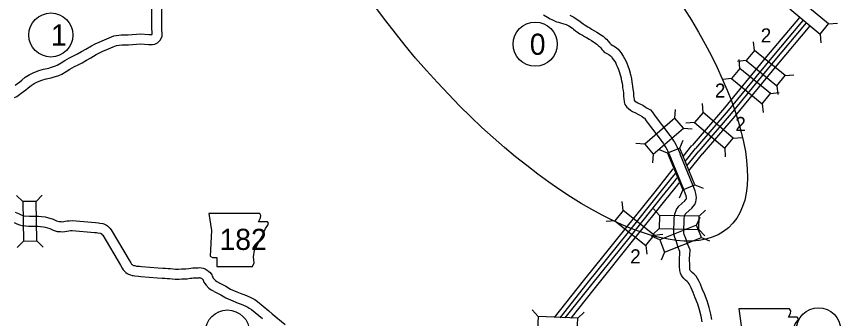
# Model space of a CAD drawing. Extents: x 1369979 to 1371646, y 379997 to 381064.
# Drawn here: x 1370115.6 to 1370308.4, y 380809.4 to 380880.1 of the extents above; entities that cross this region are included whole.
import ezdxf

# ---------------------------------------------------------------- set-up
doc = ezdxf.new("R2010")
doc.units = 0
doc.layers.add('R_Border Notes', color=7, linetype='Continuous')
doc.layers.add('R_Draft', color=7, linetype='Continuous')

msp = doc.modelspace()

# ---------------------------------------------------------------- linework, layer by layer
at = {"layer": 'R_Border Notes'}
for p, q in [((1370305.57, 380878.36), (1370307.63, 380878.55)), ((1370303.59, 380875.99), (1370303.78, 380873.93)), ((1370288.25, 380872.15), (1370288.04, 380874.2)), ((1370286.28, 380869.76), (1370284.23, 380869.55)), ((1370284.81, 380867.96), (1370284.61, 380870.01)), ((1370295.42, 380866.26), (1370297.47, 380866.46)), ((1370282.85, 380865.57), (1370280.8, 380865.37)), ((1370291.99, 380862.08), (1370294.04, 380862.28)), ((1370293.46, 380863.87), (1370293.66, 380861.82)), ((1370269.58, 380856.27), (1370269.74, 380858.33)), ((1370276.24, 380857.65), (1370276.08, 380859.71)), ((1370290.03, 380859.68), (1370290.23, 380857.63)), ((1370274.22, 380855.31), (1370272.16, 380855.15)), ((1370271.6, 380853.93), (1370273.66, 380853.77)), ((1370270.78, 380849.25), (1370271.58, 380851.15)), ((1370283.27, 380851.6), (1370285.33, 380851.76)), ((1370262.55, 380850.22), (1370260.49, 380850.38)), ((1370267.92, 380848.08), (1370266.02, 380848.87)), ((1370281.26, 380849.26), (1370281.41, 380847.2)), ((1370264.56, 380847.88), (1370264.41, 380845.82)), ((1370271.44, 380839.49), (1370270.65, 380837.59)), ((1370274.31, 380840.66), (1370276.21, 380839.87)), ((1370117.07, 380836.76), (1370115.59, 380838.19)), ((1370120.16, 380836.81), (1370121.6, 380838.29)), ((1370257.53, 380834.7), (1370257.3, 380836.75)), ((1370266, 380833.53), (1370264.58, 380835.02)), ((1370274.69, 380831.22), (1370275.51, 380833.12)), ((1370275.28, 380833.32), (1370276.77, 380834.75)), ((1370255.59, 380832.28), (1370253.54, 380832.05)), ((1370265.93, 380830.44), (1370264.44, 380829.01)), ((1370275.21, 380830.23), (1370276.64, 380828.74)), ((1370117.21, 380827.48), (1370115.78, 380826)), ((1370120.31, 380827.53), (1370121.79, 380826.09)), ((1370266.06, 380827.81), (1370264.16, 380828.64)), ((1370264.78, 380828.9), (1370266.83, 380829.13)), ((1370275.82, 380828.35), (1370277.72, 380827.53)), ((1370262.85, 380826.49), (1370263.08, 380824.44)), ((1370267.19, 380824.94), (1370266.37, 380823.05)), ((1370237.6, 380809.85), (1370236.21, 380811.37)), ((1370246.88, 380809.44), (1370248.4, 380810.84))]:
    msp.add_line(p, q, dxfattribs=at)
for points in [[(1370115.14, 380861.16), (1370115.63, 380861.4), (1370116.26, 380861.81), (1370116.68, 380862.16), (1370117.22, 380862.54), (1370117.79, 380862.96), (1370118.3, 380863.39), (1370118.99, 380863.93), (1370119.72, 380864.39), (1370120.47, 380864.81), (1370121.54, 380865.21), (1370122.49, 380865.51), (1370123.67, 380865.76), (1370124.16, 380865.9), (1370125.51, 380866.32), (1370126.2, 380866.61), (1370127.2, 380867.24), (1370128.1, 380867.74), (1370129.16, 380868.37), (1370129.82, 380868.72), (1370130.93, 380869.25), (1370131.99, 380869.84), (1370132.99, 380870.44), (1370134.26, 380871.23), (1370134.98, 380871.61), (1370135.81, 380871.96), (1370137.13, 380872.5), (1370138.19, 380872.97), (1370139.01, 380873.28), (1370140.22, 380873.49), (1370141.8, 380873.44), (1370144.63, 380873.67), (1370146.46, 380873.52), (1370146.91, 380873.53), (1370147.38, 380873.55), (1370147.91, 380873.61), (1370148.61, 380873.9), (1370149.21, 380874.58), (1370149.69, 380875.43), (1370149.62, 380877.72), (1370149.7, 380890.06)], [(1370115.26, 380864.03), (1370115.85, 380864.44), (1370116.33, 380864.8), (1370116.82, 380865.21), (1370117.65, 380865.86), (1370118.52, 380866.41), (1370119.48, 380866.94), (1370120.78, 380867.43), (1370121.9, 380867.78), (1370123.12, 380868.04), (1370123.51, 380868.15), (1370124.7, 380868.52), (1370125.11, 380868.7), (1370126, 380869.25), (1370126.93, 380869.77), (1370128.02, 380870.42), (1370128.77, 380870.82), (1370129.85, 380871.33), (1370130.81, 380871.87), (1370131.77, 380872.44), (1370133.1, 380873.27), (1370133.99, 380873.73), (1370134.9, 380874.12), (1370136.21, 380874.65), (1370137.29, 380875.14), (1370138.39, 380875.56), (1370140.05, 380875.84), (1370141.74, 380875.79), (1370144.63, 380876.02), (1370146.55, 380875.87), (1370146.86, 380875.87), (1370147.18, 380875.88), (1370147.24, 380875.89), (1370147.29, 380875.95), (1370147.33, 380876.01), (1370147.27, 380877.69), (1370147.36, 380890.18)], [(1370238.9, 380880.48), (1370239.84, 380879.93), (1370240.47, 380879.58), (1370240.83, 380879.39), (1370241.42, 380879.1), (1370241.89, 380878.89), (1370242.42, 380878.74), (1370243.05, 380878.54), (1370243.66, 380878.37), (1370244.18, 380878.21), (1370244.78, 380877.93), (1370245.64, 380877.35), (1370245.93, 380877.12), (1370246.38, 380876.78), (1370246.83, 380876.42), (1370247.4, 380876.08), (1370248, 380875.71), (1370248.5, 380875.42), (1370248.95, 380875.16), (1370249.59, 380874.77), (1370250.1, 380874.45)], [(1370245.03, 380880.4), (1370245.95, 380879.97), (1370247.01, 380879.25), (1370247.34, 380878.99), (1370247.82, 380878.63), (1370248.18, 380878.35), (1370248.61, 380878.08), (1370249.21, 380877.72), (1370249.68, 380877.44), (1370250.14, 380877.17), (1370250.82, 380876.76), (1370251.34, 380876.43)], [(1370298.77, 380879.89), (1370291.05, 380870.71), (1370281.23, 380858.74), (1370273.65, 380849.92)], [(1370299.58, 380879.19), (1370291.88, 380870.03), (1370282.05, 380858.05), (1370274.46, 380849.22)], [(1370300.35, 380878.59), (1370292.63, 380869.4), (1370282.8, 380857.42), (1370275.2, 380848.58)], [(1370301.18, 380877.9), (1370293.46, 380868.72), (1370283.62, 380856.73), (1370276.02, 380847.88)], [(1370251.36, 380876.42), (1370252.41, 380875.73), (1370252.81, 380875.46), (1370253.28, 380875.03), (1370253.59, 380874.77), (1370254, 380874.34), (1370254.39, 380873.87), (1370254.59, 380873.61), (1370254.73, 380873.52), (1370255.1, 380873.32), (1370255.39, 380873.17), (1370255.93, 380872.79), (1370256.33, 380872.47), (1370256.66, 380872.1), (1370256.94, 380871.64), (1370257.52, 380870.79), (1370257.81, 380870.29), (1370258.1, 380869.73), (1370258.34, 380869.19), (1370258.64, 380868.54), (1370258.93, 380867.67), (1370259.31, 380866.2), (1370259.38, 380865.87), (1370259.46, 380865.47), (1370259.56, 380864.81), (1370259.64, 380864.29), (1370259.71, 380863.75), (1370259.8, 380863.11), (1370259.94, 380862.3), (1370259.93, 380861.83), (1370259.94, 380861.52), (1370259.97, 380861.17), (1370260.05, 380860.63), (1370260.09, 380860.5), (1370260.15, 380860.41), (1370260.19, 380860.36), (1370260.54, 380860.14), (1370260.91, 380859.9), (1370261.42, 380859.63), (1370262.12, 380859.3), (1370262.64, 380858.97), (1370263.16, 380858.67), (1370263.87, 380858.23), (1370264.33, 380857.74), (1370264.83, 380856.99), (1370265.22, 380856.48), (1370267.97, 380852.83), (1370268.13, 380852.64), (1370268.45, 380852.23), (1370268.8, 380851.75), (1370269.03, 380851.41), (1370269.27, 380850.99), (1370269.49, 380850.68), (1370269.93, 380849.94), (1370270.06, 380849.62), (1370270.84, 380847.91)], [(1370250.08, 380874.46), (1370251.1, 380873.79), (1370251.35, 380873.62), (1370251.73, 380873.27), (1370251.99, 380873.05), (1370252.25, 380872.78), (1370252.55, 380872.41), (1370252.84, 380872.03), (1370253.09, 380871.78), (1370253.55, 380871.49), (1370254, 380871.26), (1370254.17, 380871.17), (1370254.52, 380870.92), (1370254.71, 380870.77), (1370254.77, 380870.7), (1370254.97, 380870.37), (1370255.54, 380869.54), (1370255.76, 380869.16), (1370255.99, 380868.72), (1370256.2, 380868.23), (1370256.45, 380867.68), (1370256.68, 380867), (1370257.03, 380865.67), (1370257.08, 380865.39), (1370257.15, 380865.06), (1370257.24, 380864.46), (1370257.32, 380863.96), (1370257.39, 380863.43), (1370257.49, 380862.74), (1370257.59, 380862.14), (1370257.58, 380861.83), (1370257.6, 380861.37), (1370257.64, 380860.89), (1370257.75, 380860.13), (1370257.94, 380859.5), (1370258.34, 380858.89), (1370258.73, 380858.52), (1370259.26, 380858.17), (1370259.72, 380857.87), (1370260.37, 380857.53), (1370260.98, 380857.24), (1370261.43, 380856.96), (1370261.96, 380856.65), (1370262.37, 380856.4), (1370262.49, 380856.27), (1370262.92, 380855.63), (1370263.34, 380855.07), (1370266.14, 380851.36), (1370266.32, 380851.15), (1370266.57, 380850.83), (1370266.89, 380850.4), (1370267.05, 380850.16), (1370267.28, 380849.75), (1370267.51, 380849.41), (1370267.83, 380848.89), (1370267.91, 380848.69), (1370268.7, 380846.94)], [(1370271.56, 380847.31), (1370273.61, 380849.88)], [(1370271.98, 380846.13), (1370274.45, 380849.21)], [(1370272.43, 380845.13), (1370275.21, 380848.6)], [(1370276.01, 380808.59), (1370275.74, 380809.91), (1370275.4, 380811.36), (1370274.99, 380812.73), (1370274.34, 380814.22), (1370273.85, 380815.47), (1370273.42, 380816.52), (1370273.2, 380817.02), (1370272.94, 380817.48), (1370272.73, 380817.79), (1370272.51, 380818.02), (1370272.08, 380818.37), (1370271.73, 380818.72), (1370271.48, 380819.04), (1370271.19, 380819.46), (1370270.95, 380819.96), (1370270.75, 380820.58), (1370270.72, 380821.57), (1370270.72, 380823.59), (1370270.77, 380824.33), (1370270.79, 380825.03), (1370270.38, 380826.03), (1370269.97, 380827.35), (1370269.58, 380828.33), (1370269.38, 380829.18), (1370269.46, 380832.97), (1370269.58, 380833.81), (1370269.96, 380834.91), (1370270.53, 380835.66), (1370271.91, 380836.89), (1370272.21, 380837.22), (1370272.25, 380837.34), (1370272.29, 380837.5), (1370272.3, 380837.69), (1370272.25, 380838.11), (1370272.12, 380838.5), (1370271.72, 380839.58), (1370268.69, 380846.98)], [(1370278.29, 380809.16), (1370278.03, 380810.42), (1370277.66, 380811.97), (1370277.2, 380813.53), (1370276.5, 380815.12), (1370276.02, 380816.35), (1370275.58, 380817.43), (1370275.3, 380818.07), (1370274.94, 380818.7), (1370274.56, 380819.27), (1370274.1, 380819.75), (1370273.66, 380820.11), (1370273.49, 380820.28), (1370273.36, 380820.44), (1370273.22, 380820.64), (1370273.12, 380820.84), (1370273.08, 380820.98), (1370273.07, 380821.6), (1370273.06, 380823.52), (1370273.11, 380824.21), (1370273.15, 380825.45), (1370272.59, 380826.83), (1370272.18, 380828.14), (1370271.82, 380829.04), (1370271.73, 380829.43), (1370271.8, 380832.78), (1370271.87, 380833.26), (1370272.05, 380833.78), (1370272.26, 380834.06), (1370273.57, 380835.23), (1370274.29, 380836.03), (1370274.51, 380836.72), (1370274.61, 380837.13), (1370274.66, 380837.72), (1370274.55, 380838.63), (1370274.33, 380839.28), (1370273.91, 380840.43), (1370270.86, 380847.87)], [(1370272.89, 380843.98), (1370276.05, 380847.92)], [(1370264.96, 380839.07), (1370267.83, 380842.66), (1370269.24, 380844.42)], [(1370265.85, 380838.47), (1370268.67, 380841.99), (1370269.77, 380843.36)], [(1370266.67, 380837.92), (1370269.43, 380841.38), (1370270.18, 380842.31)], [(1370267.56, 380837.32), (1370270.27, 380840.71), (1370270.63, 380841.16)], [(1370241.44, 380809.61), (1370248.27, 380818.2), (1370257.91, 380830.24), (1370264.96, 380839.07)], [(1370242.78, 380809.56), (1370249.11, 380817.53), (1370258.75, 380829.57), (1370265.85, 380838.47)], [(1370243.97, 380809.5), (1370249.88, 380816.92), (1370259.51, 380828.96), (1370266.67, 380837.92)], [(1370245.32, 380809.46), (1370250.72, 380816.25), (1370260.35, 380828.29), (1370267.56, 380837.32)], [(1370115.28, 380834.31), (1370116.02, 380833.97), (1370116.67, 380833.68), (1370117.04, 380833.51), (1370117.33, 380833.43), (1370118.59, 380833.31), (1370119.9, 380833.33), (1370120.74, 380833.32), (1370121.44, 380833.24), (1370122.26, 380833.15), (1370122.87, 380833.03), (1370124.18, 380832.61), (1370124.98, 380832.26), (1370125.53, 380832.09), (1370126.04, 380832.06), (1370126.34, 380832.04), (1370126.99, 380832.14), (1370127.47, 380832.22), (1370127.94, 380832.28), (1370128.6, 380832.35), (1370134.04, 380831.88), (1370134.77, 380831.81), (1370135.08, 380831.72), (1370135.82, 380831.63), (1370136.02, 380831.54), (1370136.17, 380831.49), (1370136.66, 380831.26), (1370136.91, 380831.09), (1370137.12, 380830.85), (1370137.43, 380830.53), (1370137.71, 380830.16), (1370141.95, 380823.05), (1370142.31, 380822.41), (1370142.5, 380822.13), (1370142.62, 380822.03), (1370142.77, 380821.87), (1370142.78, 380821.87), (1370142.92, 380821.82), (1370143.1, 380821.77), (1370143.29, 380821.75), (1370143.67, 380821.66), (1370144.35, 380821.6), (1370144.82, 380821.56), (1370148.76, 380821.25), (1370149.8, 380821.17), (1370150.46, 380821.14), (1370151.03, 380821.09), (1370151.62, 380821.04), (1370152.25, 380820.97), (1370152.78, 380820.92), (1370153.52, 380820.93), (1370154.22, 380820.97), (1370154.87, 380820.97), (1370155.18, 380821.02), (1370155.89, 380821.11), (1370156.38, 380821.17), (1370156.81, 380821.21), (1370157.24, 380821.21), (1370157.54, 380821.21), (1370158.09, 380821.27), (1370158.49, 380821.29), (1370158.85, 380821.25), (1370159.29, 380821.14), (1370159.7, 380820.97), (1370160.22, 380820.66), (1370160.58, 380820.4), (1370160.91, 380820.12), (1370161.25, 380819.6), (1370161.38, 380819.31), (1370161.51, 380819.03), (1370161.63, 380818.84), (1370161.75, 380818.67), (1370162.13, 380818.28), (1370162.43, 380818.06), (1370162.92, 380817.78)], [(1370115.05, 380831.84), (1370115.7, 380831.55), (1370116.25, 380831.29), (1370116.92, 380831.12), (1370118.49, 380830.97), (1370119.89, 380830.99), (1370120.59, 380830.97), (1370121.19, 380830.91), (1370121.9, 380830.83), (1370122.28, 380830.76), (1370123.35, 380830.42), (1370124.15, 380830.06), (1370125.11, 380829.76), (1370125.9, 380829.72), (1370126.46, 380829.68), (1370127.37, 380829.83), (1370127.81, 380829.9), (1370128.21, 380829.95), (1370128.61, 380829.99), (1370133.83, 380829.54), (1370134.33, 380829.5), (1370134.6, 380829.41), (1370135.2, 380829.34), (1370135.29, 380829.31), (1370135.4, 380829.26), (1370135.65, 380829), (1370135.76, 380828.85), (1370139.92, 380821.87), (1370140.3, 380821.19), (1370140.56, 380820.8), (1370140.74, 380820.54), (1370141.04, 380820.29), (1370141.2, 380820.13), (1370141.44, 380819.93), (1370141.82, 380819.72), (1370142.25, 380819.57), (1370142.66, 380819.46), (1370142.88, 380819.44), (1370143.29, 380819.34), (1370144.14, 380819.26), (1370144.64, 380819.22), (1370148.58, 380818.91), (1370149.65, 380818.83), (1370150.32, 380818.8), (1370150.83, 380818.76), (1370151.39, 380818.7), (1370152.02, 380818.64), (1370152.69, 380818.58), (1370153.61, 380818.59), (1370154.29, 380818.63), (1370155.03, 380818.63), (1370155.5, 380818.69), (1370156.18, 380818.79), (1370156.63, 380818.84), (1370156.93, 380818.87), (1370157.21, 380818.87), (1370157.65, 380818.86), (1370158.29, 380818.93), (1370158.41, 380818.94), (1370158.42, 380818.94), (1370158.56, 380818.91), (1370158.65, 380818.87), (1370158.93, 380818.7), (1370159.12, 380818.56), (1370159.14, 380818.55), (1370159.18, 380818.48), (1370159.24, 380818.34), (1370159.45, 380817.91), (1370159.66, 380817.55), (1370159.95, 380817.16), (1370160.58, 380816.51), (1370161.14, 380816.09), (1370161.76, 380815.74)], [(1370162.87, 380817.81), (1370164.59, 380816.93), (1370165.64, 380816.26), (1370167.12, 380815.64), (1370168.33, 380815.13), (1370169.03, 380814.88), (1370170.24, 380814.36), (1370170.85, 380814.06), (1370171.31, 380813.78), (1370171.98, 380813.33), (1370174.64, 380811.14), (1370175.41, 380810.49), (1370178.46, 380807.96)], [(1370161.8, 380815.72), (1370163.42, 380814.89), (1370164.55, 380814.17), (1370166.21, 380813.48), (1370167.48, 380812.95), (1370168.17, 380812.7), (1370169.26, 380812.23), (1370169.73, 380812), (1370170.05, 380811.8), (1370170.57, 380811.45), (1370173.14, 380809.33)]]:
    msp.add_lwpolyline(points, dxfattribs=at)
for points in [[(1370305.57, 380878.36), (1370298.45, 380884.31), (1370296.47, 380881.93), (1370303.59, 380875.99)], [(1370286.28, 380869.76), (1370293.46, 380863.87), (1370295.42, 380866.26), (1370288.25, 380872.15)], [(1370282.85, 380865.57), (1370290.03, 380859.68), (1370291.99, 380862.08), (1370284.81, 380867.96)], [(1370269.58, 380856.27), (1370262.55, 380850.22), (1370264.56, 380847.88), (1370271.6, 380853.93)], [(1370274.22, 380855.31), (1370281.26, 380849.26), (1370283.27, 380851.6), (1370276.24, 380857.65)], [(1370274.31, 380840.66), (1370270.78, 380849.25), (1370267.92, 380848.08), (1370271.44, 380839.49)], [(1370120.31, 380827.53), (1370120.16, 380836.81), (1370117.07, 380836.76), (1370117.21, 380827.48)], [(1370160.59, 380833.98), (1370161.18, 380830.01), (1370160.92, 380824), (1370161.45, 380823.67), (1370162.44, 380823.67), (1370162.44, 380821.55), (1370170.77, 380821.55), (1370171.16, 380822.41), (1370171.03, 380823.8), (1370171.23, 380825.38), (1370171.96, 380826.64), (1370172.42, 380827.57), (1370173.08, 380828.56), (1370173.48, 380829.61), (1370173.81, 380830.47), (1370174.4, 380831.2), (1370174.53, 380831.66), (1370174.27, 380831.99), (1370172.22, 380831.99), (1370172.68, 380832.92), (1370172.75, 380833.51), (1370172.48, 380833.97)], [(1370264.78, 380828.9), (1370257.53, 380834.7), (1370255.59, 380832.28), (1370262.85, 380826.49)], [(1370265.93, 380830.44), (1370275.21, 380830.23), (1370275.28, 380833.32), (1370266, 380833.53)], [(1370274.69, 380831.22), (1370266.06, 380827.81), (1370267.19, 380824.94), (1370275.82, 380828.35)], [(1370284.55, 380811.63), (1370285.15, 380807.67), (1370284.88, 380801.65), (1370285.41, 380801.32), (1370286.4, 380801.32), (1370286.4, 380799.21), (1370294.73, 380799.21), (1370295.13, 380800.07), (1370294.99, 380801.45), (1370295.19, 380803.04), (1370295.92, 380804.3), (1370296.38, 380805.22), (1370297.04, 380806.21), (1370297.44, 380807.27), (1370297.77, 380808.13), (1370298.36, 380808.86), (1370298.5, 380809.32), (1370298.23, 380809.65), (1370296.18, 380809.65), (1370296.65, 380810.57), (1370296.71, 380811.17), (1370296.44, 380811.63)], [(1370246.88, 380809.44), (1370237.6, 380809.85), (1370237.47, 380806.76), (1370246.74, 380806.35)]]:
    msp.add_lwpolyline(points, close=True, dxfattribs=at)
for centre in [(1370123.64, 380875.77), (1370236.94, 380873.61), (1370164.92, 380806.21), (1370303.2, 380806.72)]:
    msp.add_circle(centre, 5.16, dxfattribs=at)
at = {"layer": 'R_Draft'}
msp.add_ellipse((1370232.85, 380886.38), major_axis=(49.3, -55.76), ratio=0.383373, dxfattribs=at)

# ---------------------------------------------------------------- texts
at = {"layer": 'R_Border Notes'}
for s, height, p in [('1', 4.95, (1370123.64, 380873.3)), ('0', 4.95, (1370235.67, 380871.13)), ('2', 3.3, (1370289.7, 380874.02)), ('2', 3.3, (1370278.97, 380861.09)), ('2', 3.3, (1370283.75, 380853.27)), ('182', 4.95, (1370163.08, 380825.43)), ('2', 3.3, (1370259.16, 380822.27))]:
    msp.add_text(s, height=height, dxfattribs=at).set_placement(p)

doc.saveas('drawing.dxf')
